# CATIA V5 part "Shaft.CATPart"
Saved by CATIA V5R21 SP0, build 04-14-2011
Part number:  Shaft
Bounding box of the stored display mesh (mm): x -100 to 100, y 0 to 599.92, z -100 to 100
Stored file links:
  C:\Users\riadm\Desktop\Jet_Engine\Shaft.CATPart
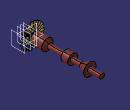
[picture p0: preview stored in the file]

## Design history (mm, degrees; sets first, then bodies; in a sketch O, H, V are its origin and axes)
Body1 (main body)
  Sketch1 on yz-plane, origin (0, 0, 0), H (0, 1, 0), V (0, 0, 1)
    line L1 (0, 0) -> (0, 20)
    line L2 (0, 20) -> (30, 20)
    point P2 (30, 20)
    line L3 (30, 20) -> (50, 46.917)
    point P3 (50, 46.917)
    line L4 (50, 46.917) -> (145, 46.917)
    line L5 (145, 46.917) -> (165, 20)
    line L6 (165, 20) -> (299, 20)
    line L7 (299, 20) -> (299, 41.11)
    line L8 (299, 41.11) -> (356, 41.11)
    line L9 (356, 41.11) -> (356, 20)
    point P9 (356, 20)
    line L10 (356, 20) -> (434.92, 20)
    line L11 (434.92, 20) -> (499.92, 51.667)
    line L12 (499.92, 51.667) -> (499.92, 20)
    point P12 (499.92, 20)
    line L13 (499.92, 20) -> (599.92, 20)
    line L14 (599.92, 20) -> (599.92, 0)
    point P14 (599.92, 0)
    line L15 (599.92, 0) -> (0, 0)
    length L2 = 30
    length L4 = 95
    distance P2 P3 H = 20
    length L5 H = 20
    length L6 = 134
    length L8 = 57
    length L10 = 78.92
    length L11 H = 65
    length L1 = 20
    length L7 = 21.11
    length L13 = 100
    length L3 V = 26.917
    length L12 = 31.667
    vertical: L1 V, L7 V, L9 V, L12 V, L14 V
    horizontal: L2 H, L4 H, L6 H, L8 H, L10 H, L13 H, L15 H
    coincidence: P9 L6, P12 L6, P14 H, L6 L2
  Shaft1: profile Sketch1, axis Sketch1.L15, angle 360
  Plane1: type Offset, RefPlane yz-plane, Offset 21
  Sketch2 on Plane1, origin (21, 0, 0), H (0, 1, 0), V (0, 0, 1)
    spline S1 through (0.5, -1.265) (5.809, 0) (16.872, 1.757) (24.64, 2.262)
    spline S2 through (0.5, -1.265) (7.078, -1.123) (15.972, -0.2043) (24.64, 2.262)
    point P1 (0.5, -1.265)
    point P2 (0.5, -1.265)
    point P3 (24.64, 2.262)
    point P4 (24.64, 2.262)
    point P5 (5.809, 0)
    point P6 (16.872, 1.757)
    point P7 (7.078, -1.123)
    point P8 (15.972, -0.2043)
    distance P2 V = 0.5
    distance P2 H = 1.265
    distance V P5 = 5.809
    distance P6 V = 16.872
    distance P3 V = 24.64
    distance P3 H = 2.262
    distance P7 V = 7.078
    distance P7 H = 1.123
    distance P8 V = 15.972
    distance P6 H = 1.757
    coincidence: P2 P1, P3 P4, P5 H
  Plane2: type Offset, RefPlane yz-plane, Offset 50
  Sketch3 on Plane2, origin (50, 0, 0), H (0, 1, 0), V (0, 0, 1)
    arc A1 centre (855.0494, -1334.1174) radius 1579.273 from (2.168, -4.946) to (19.856, 6.239) cw
    point P2 (2.168, -4.946)
    point P3 (19.856, 6.239)
    arc A2 centre (-10.851, 35.2208) radius 42.224 from (2.168, -4.946) to (19.856, 6.239) ccw
    distance P2 H = 4.946
    distance P2 V = 2.168
    radius A1 = 1579.273
    radius A2 = 42.224
    distance P3 H = 6.239
    distance P3 V = 19.856
  Plane3: type Offset, RefPlane yz-plane, Offset 100
  Sketch4 on Plane3, origin (100, 0, 0), H (0, 1, 0), V (0, 0, 1)
    arc A1 centre (8.2454, 6.07) radius 12.453 from (13.209, -5.351) to (20.514, 8.205) ccw
    point P1 (13.209, -5.351)
    point P2 (20.514, 8.205)
    arc A2 centre (-5.037, 13.2276) radius 26.04 from (13.209, -5.351) to (20.514, 8.205) ccw
    distance P1 V = 13.209
    distance P1 H = 5.351
    radius A1 = 12.453
    radius A2 = 26.04
    distance P2 H = 8.205
    distance P2 P1 H = 7.305
  Pad1: profile Sketch2, direction (1, 0, 0), up to the existing solid (limit type 2)
  DatumCurve1
  DatumCurve2
  Circle1 to Circle4: stored without definition
  Curve1: Elements (vertex of DatumCurve1; vertex of Circle1; vertex of Circle3)
  Curve2: Elements (vertex of DatumCurve1; vertex of Circle1; vertex of Circle3)
  Join1: Elements (DatumCurve2; DatumCurve1)
  Join2: Elements (Circle2; Circle1)
  Join3: Elements (Circle4; Circle3)
  Loft1: Sections (Join1; Join2; Join3), Guides (Curve1; Curve2)
  Fill1: Boundary (edge of Loft1; edge of Loft1)
  Fill2: Boundary (edge of Loft1; edge of Loft1)
  Join4: Elements (Fill2; Loft1; Fill1)
  CloseSurface1: CloseElement Join4
  CircPattern1: of Pad1, instances 25, angular step 15, axis from Y axis
  CircPattern2: of CloseSurface1, instances 25, angular step 15, axis from Y axis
